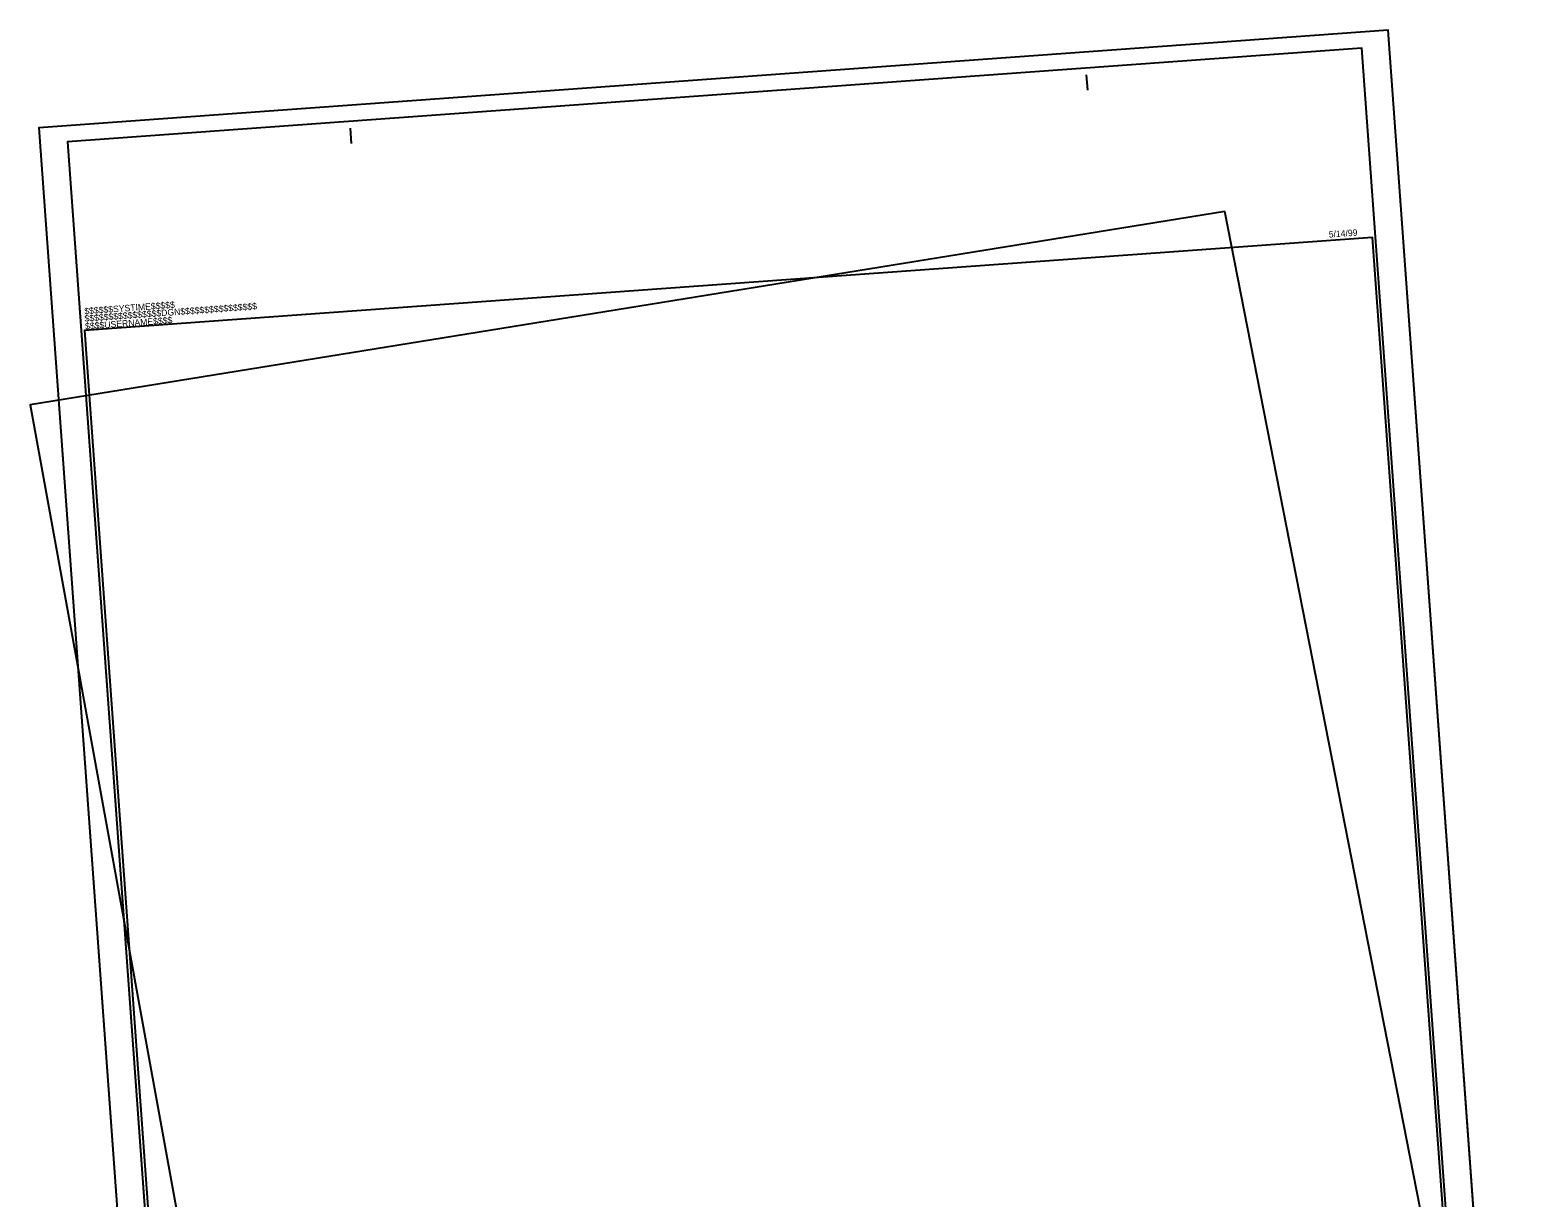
# Model space of a CAD drawing. Extents: x 2130580 to 2131806, y 642587 to 644485.
# Drawn here: x 2130580 to 2131806, y 643536 to 644485 of the extents above; entities that cross this region are included whole.
import ezdxf

# ---------------------------------------------------------------- set-up
doc = ezdxf.new("R2010")
doc.units = 0
for name, color, linetype in [('Scratch_Level_1', 7, 'Continuous'), ('Sheet Border Standard 30in CELL', 7, 'Continuous'), ('Sheet Cutting Line CELL', 7, 'Continuous'), ('Sheet Plot Border Inside CELL', 7, 'Continuous'), ('Sheet Plot Border Outside CELL', 7, 'Continuous')]:
    doc.layers.add(name, color=color, linetype=linetype)

msp = doc.modelspace()

# ---------------------------------------------------------------- linework, layer by layer
at = {"layer": 'Scratch_Level_1'}
msp.add_lwpolyline([(2131551.1, 644337.9), (2130579.8, 644180.7), (2130824.5, 642834.6), (2131607.1, 642983.6), (2131586, 643119), (2131781.2, 643164.2)], close=True, dxfattribs=at)
at = {"layer": 'Sheet Border Standard 30in CELL'}
for p, q in [((2131438.5, 644449), (2131439.4, 644436.5)), ((2130840, 644405.6), (2130840.9, 644393.2)), ((2131671.2, 644315.9), (2131671.2, 644315.9))]:
    msp.add_line(p, q, dxfattribs=at)
msp.add_lwpolyline([(2131779.5, 642820.9), (2131671.1, 644316.9), (2130623.9, 644241.1), (2130732.2, 642745)], close=True, dxfattribs=at)
at = {"layer": 'Sheet Cutting Line CELL'}
for p, q in [((2131684, 644485.3), (2130586.9, 644405.8)), ((2131805.6, 642805.7), (2131684, 644485.3)), ((2130586.9, 644405.8), (2130708.5, 642726.2))]:
    msp.add_line(p, q, dxfattribs=at)
at = {"layer": 'Sheet Plot Border Inside CELL'}
msp.add_lwpolyline([(2131782.9, 642808.6), (2131662.5, 644470.7), (2130610.2, 644394.5), (2130730.6, 642732.3)], close=True, dxfattribs=at)
at = {"layer": 'Sheet Plot Border Outside CELL'}
msp.add_lwpolyline([(2131805.6, 642805.7), (2131684, 644485.3), (2130586.9, 644405.8), (2130708.5, 642726.2)], close=True, dxfattribs=at)

# ---------------------------------------------------------------- texts
at = {"layer": 'Sheet Border Standard 30in CELL'}
for s, p in [('5/14/99', (2131635.8, 644316.6)), ('$$$$$$SYSTIME$$$$$', (2130624, 644254.3)), ('$$$$$$$$$$$$$$$$DGN$$$$$$$$$$$$$$$$', (2130624.2, 644248.3)), ('$$$$USERNAME$$$$', (2130624.7, 644242))]:
    msp.add_text(s, height=5.25, rotation=4.143, dxfattribs=at).set_placement(p)

doc.saveas('drawing.dxf')
